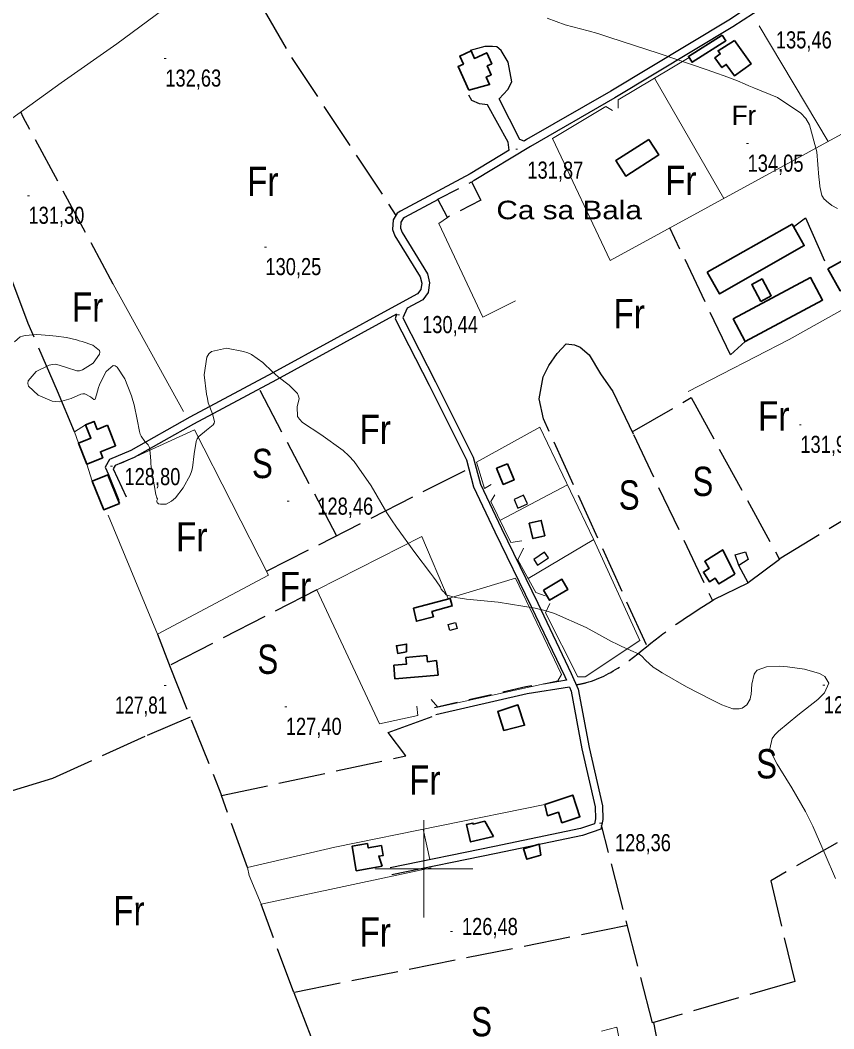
# Model space of a CAD drawing. Extents: x 483855 to 488461, y 4388206 to 4391419.
# Drawn here: x 484293 to 484710, y 4389918 to 4390435 of the extents above; entities that cross this region are included whole.
import ezdxf
from ezdxf.enums import TextEntityAlignment as Align

# ---------------------------------------------------------------- set-up
doc = ezdxf.new("R2010")
doc.units = 0
doc.header["$LTSCALE"] = 4
doc.linetypes.add('LONG_DASHED', pattern=[7.5, 6, -1.5])
doc.linetypes.add('MEDIUM_DASHED', pattern=[4.5, 3, -1.5])
for name, color, linetype, lineweight in [('1', 7, 'Continuous', 13), ('21', 7, 'Continuous', 25), ('25', 7, 'LONG_DASHED', 25), ('38', 7, 'Continuous', 25), ('47', 7, 'Continuous', 35), ('48', 7, 'MEDIUM_DASHED', 25), ('51', 7, 'Continuous', 13), ('7', 7, 'Continuous', 13), ('9', 7, 'Continuous', 13)]:
    doc.layers.add(name, color=color, linetype=linetype, lineweight=lineweight)
doc.layers.add('31', color=7, linetype='Continuous')
doc.layers.add('5', color=7, linetype='Continuous')

msp = doc.modelspace()

# ---------------------------------------------------------------- linework, layer by layer
at = {"layer": '1'}
for p, q in [((484500, 4390025), (484500, 4389975)), ((484475, 4390000), (484525, 4390000))]:
    msp.add_line(p, q, dxfattribs=at)
at = {"layer": '21'}
for points in [[(484548.17, 4390184.77), (484553.05, 4390187), (484551.01, 4390191.45), (484546.13, 4390189.22)], [(484558.2, 4390155.53), (484563.76, 4390159.28), (484561.79, 4390162.21), (484556.23, 4390158.46)], [(484661.27, 4390155.4), (484659.46, 4390160.8), (484664.71, 4390162.46), (484666.06, 4390158.48)], [(484513.25, 4390122.08), (484512.37, 4390125.13), (484516.09, 4390126.21), (484516.97, 4390123.16)]]:
    msp.add_lwpolyline(points, close=True, dxfattribs=at)
at = {"layer": '25'}
for p, q in [((484294.67, 4390385.17), (484293.56, 4390387.84)), ((484340.87, 4390299.58), (484294.67, 4390385.17)), ((484455.24, 4390170.69), (484415.64, 4390245.78)), ((484419.4, 4390152.48), (484522.93, 4390205.08)), ((484648.55, 4390137.97), (484666.08, 4390146.48)), ((484363.45, 4390120.25), (484369.92, 4390103.4)), ((484409.55, 4390000.61), (484396.36, 4390037.49)), ((484433.36, 4389936.58), (484416.63, 4389981.94)), ((484617.58, 4389921.3), (484641.49, 4389799.71))]:
    msp.add_line(p, q, dxfattribs=at)
for points in [[(484402.34, 4390466.94), (484432.13, 4390415.62), (484485.66, 4390334.8)], [(484689.38, 4390328.87), (484695.41, 4390333.46), (484706.93, 4390307.45)], [(484664.61, 4390270.18), (484657.04, 4390263.41), (484625.94, 4390328.39)], [(484320.92, 4390223.97), (484312.2, 4390244.8), (484297.26, 4390279.36), (484281.28, 4390321.92)], [(484613.96, 4390114.8), (484561.15, 4390230.55), (484559.04, 4390240.75), (484561.12, 4390252.08), (484564.03, 4390257.86), (484568.22, 4390264.09), (484572.79, 4390268.9), (484577.14, 4390268.46), (484580, 4390267.34), (484584.65, 4390263.37), (484590.37, 4390253.63), (484596.69, 4390244.56), (484607.3, 4390222.52), (484647.81, 4390137.47)], [(484606.66, 4390223.86), (484636.9, 4390241.4), (484682.19, 4390158.51), (484666.08, 4390146.48), (484661.27, 4390155.4)], [(484682.02, 4390158.82), (484789.36, 4390224.17), (484786.56, 4390237.07)], [(484445.1, 4390142.97), (484369.62, 4390104.14), (484396.36, 4390037.49), (484490.77, 4390057.9), (484481.6, 4390069.81), (484507.04, 4390079.13)], [(484841.83, 4390087.91), (484677.66, 4389993.92), (484689.9, 4389942.26), (484617.02, 4389921.13), (484590.98, 4390022.32)], [(484380.2, 4390077.77), (484357, 4390067.81), (484309.8, 4390046.3), (484262.56, 4390031.83), (484242.84, 4390024.6), (484225.52, 4390018.43)], [(484604.22, 4389970.92), (484433.36, 4389936.58), (484452.31, 4389887.36)]]:
    msp.add_lwpolyline(points, dxfattribs=at)
at = {"layer": '38'}
for points in [[(484685.36, 4390454.27), (484656.09, 4390434.82), (484595.68, 4390398.41), (484552.59, 4390373.59), (484551.38, 4390372.86)], [(484690.01, 4390452), (484658.23, 4390431.44), (484597.71, 4390394.96), (484554.62, 4390370.15), (484525.64, 4390352.58), (484524.44, 4390351.94)], [(484551.38, 4390372.86), (484549.07, 4390373.66), (484538.45, 4390394.42), (484543.02, 4390399.23), (484544.97, 4390403.2), (484543.07, 4390413.33), (484539.61, 4390419.17), (484537.36, 4390421.05), (484535.11, 4390421.34), (484531.21, 4390421.34), (484523.71, 4390419.22)], [(484543.73, 4390368.22), (484543.14, 4390372.3), (484532.61, 4390391.48), (484528.48, 4390391.85), (484524.58, 4390393.57), (484523.07, 4390396.42)], [(484543.73, 4390368.22), (484523.66, 4390356.06), (484487.91, 4390337.02), (484486.34, 4390335.9), (484484.25, 4390332.52), (484483.95, 4390327.57), (484485.16, 4390324.27), (484498.1, 4390303.36), (484498.85, 4390299.98), (484498.41, 4390296.83), (484496.76, 4390294.58), (484485.07, 4390288.26), (484422.64, 4390254.03), (484380.07, 4390231.38), (484349.79, 4390214.37), (484339, 4390209.71), (484336.71, 4390205.71), (484338.35, 4390201.95), (484343.76, 4390188.86)], [(484507.35, 4390342.84), (484490.02, 4390333.61), (484489.32, 4390333.11), (484488.18, 4390331.27), (484487.99, 4390328.16), (484488.77, 4390326.03), (484501.86, 4390304.89), (484502.91, 4390300.14), (484502.23, 4390295.28), (484499.45, 4390291.49), (484491.44, 4390287.17)], [(484485.86, 4390284.13), (484424.54, 4390250.51), (484381.99, 4390227.87), (484351.57, 4390210.78), (484341.8, 4390206.56), (484340.87, 4390204.97), (484347.4, 4390190.51)], [(484491.44, 4390287.17), (484489.24, 4390282.28), (484505.96, 4390249.5), (484525.21, 4390210.9), (484528.92, 4390197.07), (484539.71, 4390174.33), (484558.3, 4390136.04), (484575.49, 4390100.16), (484579.04, 4390092.05), (484584.55, 4390062.22), (484591.4, 4390032.2), (484591.58, 4390025.22), (484590.54, 4390020.25), (484581.17, 4390017.04), (484536.95, 4390007.78), (484483.47, 4389996.89)], [(484485.86, 4390284.13), (484485.3, 4390281.82), (484502.64, 4390247.83), (484521.72, 4390209.58), (484525.42, 4390195.78), (484536.36, 4390172.73), (484554.95, 4390134.43), (484572.11, 4390098.61), (484573.01, 4390096.58)], [(484574.52, 4390093.11), (484575.47, 4390090.95), (484580.91, 4390061.47), (484587.7, 4390031.74), (484587.86, 4390025.56), (484587.33, 4390023.08), (484580.18, 4390020.63), (484536.2, 4390011.42), (484482.73, 4390000.53)], [(484574.52, 4390093.11), (484552.88, 4390089.63), (484506.1, 4390078.91)]]:
    msp.add_lwpolyline(points, dxfattribs=at)
at = {"layer": '38', "linetype": 'MEDIUM_DASHED'}
msp.add_lwpolyline([(484573.01, 4390096.58), (484552.18, 4390093.22), (484505.28, 4390082.47)], dxfattribs=at)
at = {"layer": '38', "linetype": 'LONG_DASHED'}
msp.add_spline([(484578.05, 4390094.31), (484583.2, 4390095.41), (484620.67, 4390119.03), (484648.55, 4390137.97)], degree=3, dxfattribs=at)
at = {"layer": '47'}
for points in [[(484652.8, 4390427.16), (484635.51, 4390416.19), (484637.37, 4390413.26), (484654.66, 4390424.23)], [(484659.1, 4390424.4), (484667.6, 4390412.41), (484658.99, 4390406.3), (484654.86, 4390412.1), (484652.61, 4390410.5), (484649.01, 4390415.54), (484651.8, 4390417.54), (484650.65, 4390419.12)], [(484523.07, 4390398.89), (484517.5, 4390411.04), (484520.23, 4390412.29), (484518.36, 4390416.35), (484524.12, 4390419), (484525.85, 4390415.22), (484532.18, 4390418.11), (484534.76, 4390412.45), (484532.39, 4390411.38), (484534.45, 4390406.8), (484531.92, 4390405.67), (484533.63, 4390401.82)], [(484615.23, 4390373.69), (484598.27, 4390362.83), (484603.33, 4390354.92), (484620.29, 4390365.78)], [(484645.12, 4390305.63), (484688.54, 4390330.34), (484694.83, 4390319.28), (484651.41, 4390294.57)], [(484706.93, 4390307.45), (484746.92, 4390329.45), (484753.12, 4390318.18), (484713.13, 4390296.18)], [(484664.61, 4390270.18), (484704.2, 4390291.39), (484698.01, 4390302.94), (484658.42, 4390281.73)], [(484672.6, 4390290.74), (484667.92, 4390299.37), (484673.18, 4390302.22), (484677.86, 4390293.59)], [(484337.84, 4390227.33), (484342.06, 4390216.76), (484334.25, 4390213.66), (484335.46, 4390210.59), (484327.32, 4390207.4), (484323.12, 4390218.09), (484329.41, 4390220.57), (484326.67, 4390227.51), (484331.04, 4390229.24), (484332.67, 4390225.12)], [(484542.81, 4390207.56), (484546.2, 4390199.28), (484540.58, 4390196.98), (484537.19, 4390205.26)], [(484344.06, 4390187.21), (484338.14, 4390201.85), (484330.09, 4390198.59), (484336.01, 4390183.95)], [(484561.93, 4390170.61), (484560.06, 4390178.49), (484553.96, 4390177.05), (484555.83, 4390169.17)], [(484659.25, 4390151.04), (484651.08, 4390145.93), (484649.21, 4390148.9), (484646.26, 4390147.05), (484643.13, 4390152.01), (484646.13, 4390153.91), (484643.8, 4390157.58), (484653.09, 4390163.48)], [(484561.3, 4390142.71), (484570.66, 4390148.33), (484573.75, 4390143.18), (484564.39, 4390137.56)], [(484494.62, 4390133.52), (484513.44, 4390138.58), (484514.48, 4390134.69), (484504.08, 4390131.92), (484504.82, 4390129.11), (484496.11, 4390126.84)], [(484491.13, 4390111.09), (484486.56, 4390110.33), (484485.9, 4390114.27), (484491.11, 4390115.15)], [(484507.36, 4390099.19), (484485.16, 4390097.35), (484484.58, 4390104.27), (484491.06, 4390104.88), (484490.74, 4390108.2), (484501.46, 4390109.31), (484501.78, 4390106.13), (484506.4, 4390106.69)], [(484540.94, 4390070.81), (484537.77, 4390080.56), (484548.17, 4390083.96), (484551.57, 4390073.55)], [(484561.85, 4390033.04), (484576.25, 4390037.79), (484579.91, 4390026.69), (484570.65, 4390023.64), (484568.87, 4390029.01), (484563.3, 4390027.19)], [(484535.55, 4390016.49), (484523.85, 4390013.77), (484521.77, 4390022.68), (484525.05, 4390023.47), (484525.17, 4390022.96), (484531.17, 4390024.41)], [(484478.56, 4390001.32), (484465.29, 4389999.05), (484463.14, 4390011.56), (484471.05, 4390012.96), (484471.44, 4390010.71), (484478.23, 4390011.93), (484479.13, 4390006.88), (484476.87, 4390006.5)], [(484559.79, 4390007), (484552.67, 4390004.89), (484551.06, 4390010.28), (484559.1, 4390012.69)]]:
    msp.add_lwpolyline(points, close=True, dxfattribs=at)
at = {"layer": '48'}
msp.add_lwpolyline([(484507.18, 4390343.13), (484524.36, 4390351.9), (484529.16, 4390342.49), (484511.98, 4390333.72)], close=True, dxfattribs=at)
at = {"layer": '51'}
for p, q in [((484671.69, 4390431.84), (484706.99, 4390372.65)), ((484653.6, 4390343.5), (484618.13, 4390405.02)), ((484376.76, 4390234.22), (484340.87, 4390299.58)), ((484327.32, 4390207.4), (484330.09, 4390198.59)), ((484538.95, 4390178.51), (484573.55, 4390196.7)), ((484553.34, 4390148.72), (484587.04, 4390168.66)), ((484499.54, 4390020.29), (484503.09, 4390004.74))]:
    msp.add_line(p, q, dxfattribs=at)
for points in [[(484528.96, 4390555.31), (484496.29, 4390533.2), (484451.04, 4390500.57), (484408.63, 4390471.62), (484382.71, 4390452.3), (484342.62, 4390422.6), (484314.22, 4390402.75)], [(484599.52, 4390389.72), (484599.44, 4390393.92), (484635.9, 4390415.58)], [(484314.22, 4390402.75), (484264.72, 4390367.03), (484279.92, 4390325.99)], [(484747.32, 4390394.67), (484595.38, 4390311.7), (484565.87, 4390374.13), (484593.15, 4390390.61), (484596.53, 4390388.44)], [(484546.95, 4390290.99), (484530.09, 4390282.63), (484507.65, 4390330.68), (484511.98, 4390333.72)], [(484635.32, 4390244.47), (484687.03, 4390271.19), (484794.43, 4390331.22), (484794.36, 4390331.3), (484806.8, 4390246.78)], [(484323.12, 4390218.09), (484320.92, 4390223.97), (484326.67, 4390227.51)], [(484534.35, 4390196.97), (484531.06, 4390194.87), (484526.98, 4390208.29), (484559.36, 4390226.2), (484586.91, 4390168.93), (484610.62, 4390116.98), (484582.52, 4390098.33), (484578.77, 4390098.4), (484562.29, 4390131.23), (484564.46, 4390135.89)], [(484344.7, 4390207.69), (484382.48, 4390224.86), (484420.41, 4390150.5), (484363.45, 4390120.25), (484338.22, 4390181.2)], [(484550.15, 4390167.97), (484544.53, 4390167.13), (484534.22, 4390188.12), (484536.31, 4390191.58)], [(484546.88, 4390148.91), (484512.47, 4390138.43), (484498.84, 4390170.21), (484445.1, 4390142.97), (484477.17, 4390074.23), (484496.81, 4390078.54), (484496.43, 4390083.34)], [(484562.13, 4390139.78), (484557.25, 4390141.58), (484548.07, 4390158.29), (484550.91, 4390164.22)], [(484503.7, 4390086.8), (484507.08, 4390082.76), (484568.65, 4390096.29), (484570.52, 4390099.59), (484546.88, 4390148.91)], [(484561.85, 4390033.04), (484454.39, 4390011.03), (484409.55, 4390000.61), (484410.38, 4389996.56), (484416.63, 4389981.94), (484503.69, 4390000.46)], [(484609.05, 4389794.42), (484623.14, 4389797.37), (484598.87, 4389918.93), (484590.92, 4389916.89)]]:
    msp.add_lwpolyline(points, dxfattribs=at)
at = {"layer": '7'}
for p, q in [((484367, 4390415.12), (484368, 4390415.12)), ((484665.29, 4390371.52), (484666.29, 4390371.52)), ((484547, 4390368.7), (484548, 4390368.7)), ((484296.9, 4390344.83), (484297.9, 4390344.83)), ((484418.28, 4390318.53), (484419.28, 4390318.53)), ((484486.53, 4390283.76), (484487.53, 4390283.76)), ((484692.31, 4390227.46), (484693.31, 4390227.46)), ((484339.48, 4390206.33), (484340.48, 4390206.33)), ((484429.9, 4390188.33), (484430.9, 4390188.33)), ((484366.94, 4390093.91), (484367.94, 4390093.91)), ((484704.3, 4390094.03), (484705.3, 4390094.03)), ((484428.72, 4390083.01), (484429.72, 4390083.01)), ((484589.87, 4390023.41), (484590.87, 4390023.41)), ((484513.67, 4389967.92), (484514.67, 4389967.92))]:
    msp.add_line(p, q, dxfattribs=at)
at = {"layer": '9'}
for points in [[(484711.77, 4390338.27), (484708.92, 4390339.85), (484706.21, 4390341.99), (484705.61, 4390342.55), (484705.09, 4390343.1), (484703.76, 4390344.98), (484702.85, 4390349.5), (484702.58, 4390351.72), (484702.31, 4390354.35), (484701.28, 4390367.36), (484697.53, 4390381.19), (484695.54, 4390384.35), (484693.14, 4390387.22), (484681.03, 4390395.14), (484668.91, 4390400.11), (484666.49, 4390401.12), (484664.49, 4390401.98), (484660.67, 4390403.73), (484653.8, 4390406.3), (484649.88, 4390407.67), (484645.08, 4390409.32), (484620.46, 4390417.67), (484594.62, 4390426.15), (484589.06, 4390427.89), (484584.19, 4390429.36), (484572.35, 4390432.48), (484563.08, 4390435.85)], [(484324.21, 4390243.1), (484319.31, 4390241), (484313.31, 4390239.3), (484311.5, 4390239.36), (484309.63, 4390239.67), (484302.31, 4390242.7), (484297.46, 4390247.34), (484297.14, 4390248.64), (484297.26, 4390249.96), (484301.4, 4390254.81), (484308.06, 4390258.11), (484309.77, 4390258.44), (484311.43, 4390258.53), (484316.95, 4390256.79), (484322.17, 4390255.09), (484323.63, 4390255.21), (484325.1, 4390255.58), (484330.5, 4390259.06), (484333.79, 4390263.61), (484333.94, 4390264.65), (484333.75, 4390265.6), (484330.32, 4390268.28), (484324.85, 4390270.13), (484323.38, 4390270.56), (484321.93, 4390270.96), (484316.87, 4390272.13), (484311.53, 4390272.95), (484309.92, 4390273.12), (484308.24, 4390273.28), (484301.67, 4390273.69), (484295.69, 4390273.28), (484294.38, 4390272.93), (484293.22, 4390272.47), (484290.27, 4390269.96)], [(484503.38, 4390151.46), (484495.37, 4390162), (484485.93, 4390175.06), (484483.45, 4390178.74), (484481.05, 4390182.47), (484472.88, 4390196.18), (484464.23, 4390208.68), (484461.51, 4390211.64), (484458.66, 4390214.39), (484447.22, 4390222.49), (484437.83, 4390228.72), (484436.28, 4390230.29), (484435.18, 4390231.8), (484434.97, 4390236.65), (484436.04, 4390241.04), (484435.74, 4390242.24), (484435.18, 4390243.44), (484431, 4390247.74), (484425.35, 4390252.13), (484423.86, 4390253.38), (484422.4, 4390254.66), (484417.4, 4390259.42), (484411.64, 4390263.5), (484409.7, 4390264.34), (484407.62, 4390265.07), (484398.84, 4390266.67), (484391.17, 4390265.08), (484389.78, 4390263.8), (484388.7, 4390262.15), (484387.47, 4390253.15), (484388.63, 4390243.15), (484389.06, 4390240.88), (484389.54, 4390238.82), (484391.68, 4390233.15), (484392.69, 4390229.26), (484392.46, 4390228.32), (484392.01, 4390227.45), (484388.55, 4390224.77), (484384.6, 4390221.5), (484383.85, 4390220.25), (484383.24, 4390218.86), (484382.29, 4390212.56), (484381.44, 4390205.49), (484380.9, 4390203.6), (484380.23, 4390201.74), (484376.69, 4390195.25), (484372.66, 4390190.14), (484371.68, 4390189.14), (484370.76, 4390188.33), (484367.91, 4390186.89), (484365.81, 4390186.77), (484365.35, 4390186.77), (484364.96, 4390186.8), (484363.99, 4390187.06), (484363.49, 4390187.44), (484363.39, 4390187.55), (484363.3, 4390187.66), (484363.12, 4390188.06), (484363.11, 4390188.46), (484363.13, 4390188.57), (484363.17, 4390188.67), (484363.39, 4390189.05), (484363.54, 4390189.42), (484363.54, 4390189.53), (484363.51, 4390189.63), (484363.23, 4390190.03), (484362.67, 4390191.76), (484362.47, 4390192.7), (484362.24, 4390193.85), (484361.24, 4390199.69), (484360.33, 4390206.08), (484360.15, 4390207.57), (484360.01, 4390208.95), (484359.78, 4390212.95), (484359.36, 4390215.84), (484359.1, 4390216.52), (484358.77, 4390217.15), (484357.05, 4390218.97), (484355.13, 4390221.59), (484354.69, 4390222.72), (484354.27, 4390224.02), (484353.06, 4390230.17), (484351.49, 4390237.79), (484350.85, 4390240.02), (484350.11, 4390242.3), (484346.7, 4390250.99), (484342.82, 4390257.06), (484341.78, 4390257.69), (484340.76, 4390257.87), (484337.23, 4390254.76), (484334.39, 4390249.23), (484333.81, 4390247.89), (484333.33, 4390246.63), (484332.32, 4390242.79), (484331.58, 4390240.63), (484331.25, 4390240.44), (484330.88, 4390240.43), (484329.11, 4390241.85), (484326.33, 4390243.28), (484325.32, 4390243.28), (484324.21, 4390243.1)], [(484710.74, 4389994.98), (484705.6, 4390007.35), (484699.14, 4390021.92), (484697.28, 4390025.68), (484695.4, 4390029.31), (484688.36, 4390041.44), (484682.24, 4390051.41), (484680.94, 4390053.7), (484679.82, 4390055.77), (484677.17, 4390061.51), (484678.43, 4390066.81), (484679.77, 4390068.6), (484681.54, 4390070.53), (484691.49, 4390078.67), (484701.68, 4390086.69), (484703.6, 4390088.55), (484705.13, 4390090.25), (484707.38, 4390095.07), (484705.3, 4390098.48), (484704.09, 4390099.28), (484702.61, 4390100.03), (484694.99, 4390102.24), (484686.29, 4390103.55), (484684.12, 4390103.74), (484682.06, 4390103.84), (484675.49, 4390103.56), (484670.77, 4390101.71), (484669.87, 4390100.82), (484669.15, 4390099.78), (484668.01, 4390094.65), (484667.6, 4390089.26), (484667.35, 4390088.04), (484667.02, 4390086.95), (484665.34, 4390083.99), (484662.98, 4390082.36), (484662.24, 4390082.1), (484661.45, 4390081.93), (484658.29, 4390081.99), (484652.56, 4390084.08), (484650.16, 4390085.19), (484647.41, 4390086.53), (484634.53, 4390093.26), (484622.05, 4390100.34), (484619.55, 4390101.91), (484617.47, 4390103.3), (484613.4, 4390106.87), (484611.61, 4390109.04), (484610.97, 4390109.55), (484610.26, 4390110.01), (484607.16, 4390111.34), (484601.32, 4390113.86), (484598.89, 4390115.08), (484596.1, 4390116.51), (484583.07, 4390123.57), (484566.82, 4390130.75), (484562, 4390132.27), (484557.04, 4390133.58), (484537.97, 4390136.62), (484521.73, 4390138.24), (484518.56, 4390138.66), (484515.95, 4390139.06), (484511.33, 4390140.37), (484510.52, 4390141.43), (484510.32, 4390141.67), (484510.14, 4390141.87), (484509.56, 4390142.42), (484509.09, 4390142.93), (484508.97, 4390143.12), (484508.85, 4390143.33), (484508.45, 4390144.25), (484506.21, 4390147.62), (484504.94, 4390149.36), (484503.38, 4390151.46)]]:
    msp.add_lwpolyline(points, dxfattribs=at)

# ---------------------------------------------------------------- texts
at = {"layer": '31'}
msp.add_text('Fr', height=10, dxfattribs=at).set_placement((484663.91, 4390381.05), align=Align.CENTER)
for s, width, p in [('Fr', 0.85, (484417.46, 4390344.72)), ('Fr', 0.85, (484631.6, 4390345.19)), ('Fr', 0.85, (484327.7, 4390280.34)), ('Fr', 0.85, (484605.13, 4390276.99)), ('Fr', 0.85, (484679.19, 4390224.56)), ('Fr', 0.85, (484475.04, 4390217.65)), ('S', 0.8, (484417.23, 4390200.17)), ('S', 0.8, (484642.86, 4390191.01)), ('S', 0.8, (484605.14, 4390184.02)), ('Fr', 0.85, (484381.04, 4390162.58)), ('Fr', 0.85, (484434.13, 4390137.12)), ('S', 0.8, (484420.01, 4390099.89)), ('S', 0.8, (484675.53, 4390046.31)), ('Fr', 0.85, (484500.44, 4390038.05)), ('Fr', 0.85, (484348.87, 4389971.12)), ('Fr', 0.85, (484475.04, 4389960.11)), ('S', 0.8, (484529.51, 4389914.2))]:
    msp.add_text(s, height=15, dxfattribs=dict(at, width=width)).set_placement(p, align=Align.CENTER)
at = {"layer": '5', "width": 1.2}
msp.add_text('Ca sa Bala', height=9.5, dxfattribs=at).set_placement((484611.68, 4390332.79), align=Align.RIGHT)
at = {"layer": '7'}
for s, width, p in [('135,46', 0.8, (484680.27, 4390420.32)), ('132,63', 0.8, (484367.5, 4390400.75)), ('134,05', 0.8, (484665.79, 4390357.15)), ('131,87', 0.8, (484552.98, 4390353.6)), ('131,30', 0.8, (484297.4, 4390330.46)), ('130,25', 0.8, (484418.78, 4390304.16)), ('130,44', 0.8, (484499.06, 4390274.47)), ('131,96', 0.8, (484692.81, 4390213.09)), ('128,80', 0.8, (484346.59, 4390196.58)), ('128,46', 0.8, (484445.37, 4390181.44)), ('127,81', 0.75, (484341.67, 4390079.54)), ('129,52', 0.8, (484704.8, 4390079.66)), ('127,40', 0.8, (484429.22, 4390068.64)), ('128,36', 0.8, (484597.86, 4390009.04)), ('126,48', 0.8, (484519.46, 4389966.1))]:
    msp.add_text(s, height=8.75, dxfattribs=dict(at, width=width)).set_placement(p)

doc.saveas('drawing.dxf')
